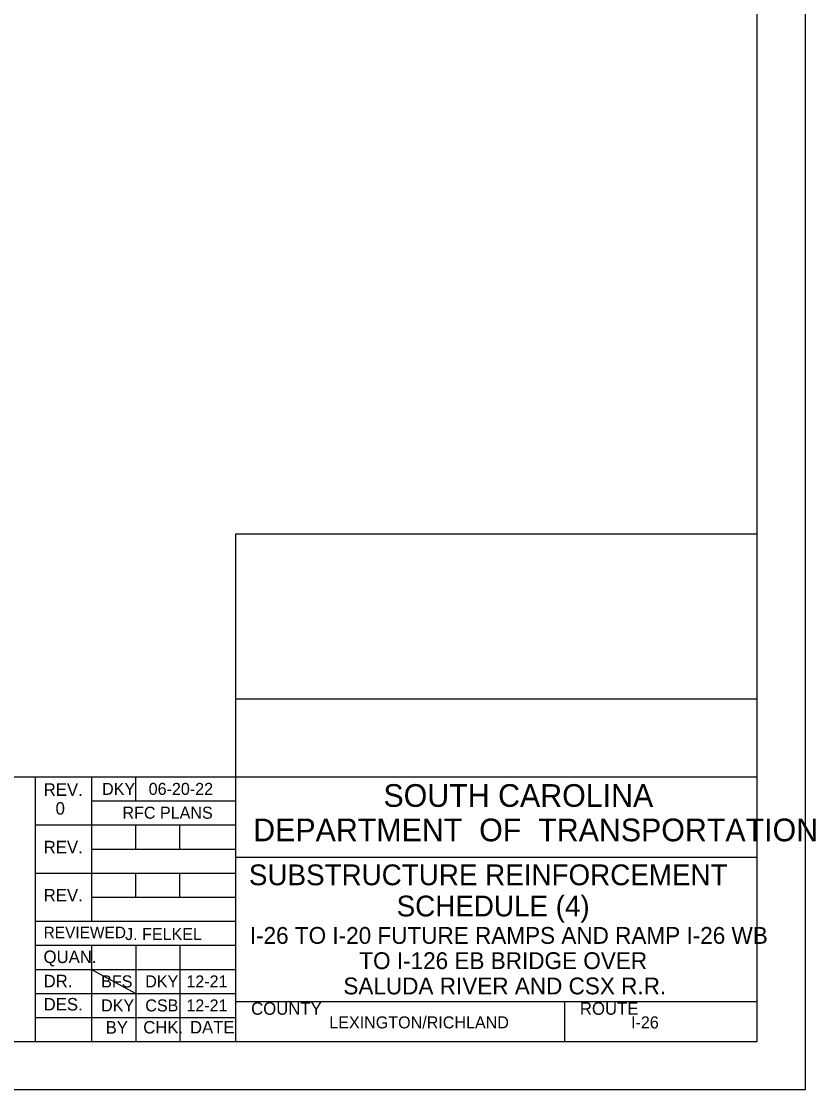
# Model space of a CAD drawing. Extents: x -121.2 to -24.9, y 6.4 to 65.6.
# Drawn here: x -46.89 to -24.88, y 6.35 to 35.95 of the extents above; entities that cross this region are included whole.
import ezdxf

# ---------------------------------------------------------------- set-up
doc = ezdxf.new("R2010")
doc.units = 0
for name, color, linetype in [('BR_BORDER LINES', 7, 'Continuous'), ('BR_TEXT', 7, 'Continuous'), ('Level 31', 7, 'Continuous')]:
    doc.layers.add(name, color=color, linetype=linetype)

msp = doc.modelspace()

# ---------------------------------------------------------------- linework, layer by layer
at = {"layer": 'BR_BORDER LINES'}
for p, q in [((-26.496, 7.683), (-26.496, 63.683)), ((-40.941, 7.683), (-40.941, 21.754)), ((-40.941, 21.754), (-26.496, 21.754)), ((-40.94, 17.182), (-26.496, 17.182)), ((-60.804, 15.017), (-46.496, 15.017)), ((-46.496, 7.683), (-46.496, 15.017)), ((-46.496, 15.017), (-26.496, 15.017)), ((-44.941, 15.017), (-44.941, 11.017)), ((-43.718, 14.35), (-43.718, 15.017)), ((-44.941, 14.35), (-40.941, 14.35)), ((-46.496, 13.684), (-40.941, 13.684)), ((-43.718, 13.017), (-43.718, 13.684)), ((-42.496, 13.017), (-42.496, 13.684)), ((-44.941, 13.017), (-40.941, 13.017)), ((-40.941, 12.795), (-40.941, 12.795)), ((-40.941, 12.795), (-26.495, 12.795)), ((-46.496, 12.35), (-40.941, 12.35)), ((-43.718, 11.684), (-43.718, 12.35)), ((-42.496, 11.684), (-42.496, 12.35)), ((-44.941, 11.684), (-40.941, 11.684)), ((-46.496, 11.017), (-40.941, 11.017)), ((-46.496, 10.35), (-40.941, 10.35)), ((-44.941, 10.35), (-44.941, 7.683)), ((-43.718, 10.35), (-43.718, 7.683)), ((-42.496, 10.35), (-42.496, 7.683)), ((-46.496, 9.683), (-40.941, 9.683)), ((-46.496, 9.017), (-40.941, 9.017)), ((-40.941, 8.795), (-26.496, 8.795)), ((-40.68, 8.795), (-26.496, 8.795)), ((-31.829, 7.683), (-31.829, 8.795)), ((-46.496, 8.35), (-40.941, 8.35)), ((-116.272, 7.683), (-26.496, 7.683))]:
    msp.add_line(p, q, dxfattribs=at)
at = {"layer": 'Level 31'}
for p, q in [((-33.717, 11.621), (-33.717, 11.621)), ((-44.941, 9.683), (-43.718, 9.017))]:
    msp.add_line(p, q, dxfattribs=at)
msp.add_lwpolyline([(-121.161, 6.35), (-25.161, 6.35), (-25.161, 65.017), (-121.161, 65.017)], close=True, dxfattribs=at)

# ---------------------------------------------------------------- texts
at = {"layer": 'BR_TEXT'}
for s, height, p in [('REV.', 0.3467, (-46.27, 14.491)), ('DKY', 0.3333, (-44.652, 14.517)), ('06-20-22', 0.3333, (-43.36, 14.517)), ('SOUTH CAROLINA', 0.62899, (-36.855, 14.186)), ('0', 0.347, (-45.94, 13.971)), ('RFC PLANS', 0.3333, (-44.087, 13.857)), ('DEPARTMENT  OF  TRANSPORTATION', 0.62899, (-40.463, 13.232)), ('REV.', 0.3467, (-46.27, 12.898)), ('SUBSTRUCTURE REINFORCEMENT', 0.576, (-40.583, 12.014)), ('REV.', 0.3467, (-46.27, 11.565)), ('SCHEDULE (4)', 0.576, (-36.489, 11.15)), ('REVIEWED', 0.32, (-46.272, 10.546)), ('J. FELKEL', 0.3333, (-44.015, 10.495)), ('I-26 TO I-20 FUTURE RAMPS AND RAMP I-26 WB', 0.46667, (-40.558, 10.39)), ('QUAN.', 0.3467, (-46.274, 9.857)), ('TO I-126 EB BRIDGE OVER', 0.46667, (-37.523, 9.69)), ('DR.', 0.3467, (-46.273, 9.186)), ('BFS', 0.3333, (-44.677, 9.183)), ('DKY', 0.3333, (-43.456, 9.183)), ('12-21', 0.3333, (-42.316, 9.183)), ('SALUDA RIVER AND CSX R.R.', 0.46667, (-37.965, 8.99)), ('DES.', 0.3467, (-46.271, 8.543)), ('DKY', 0.3333, (-44.679, 8.517)), ('CSB', 0.3333, (-43.454, 8.517)), ('12-21', 0.3333, (-42.316, 8.517)), ('COUNTY', 0.3467, (-40.521, 8.425)), ('ROUTE', 0.3467, (-31.41, 8.425)), ('LEXINGTON/RICHLAND', 0.33332, (-38.355, 8.047)), ('I-26', 0.3333, (-29.993, 8.047)), ('BY', 0.3467, (-44.553, 7.902)), ('CHK.', 0.3467, (-43.511, 7.906)), ('DATE', 0.3467, (-42.217, 7.906))]:
    msp.add_text(s, height=height, dxfattribs=at).set_placement(p)

doc.saveas('drawing.dxf')
